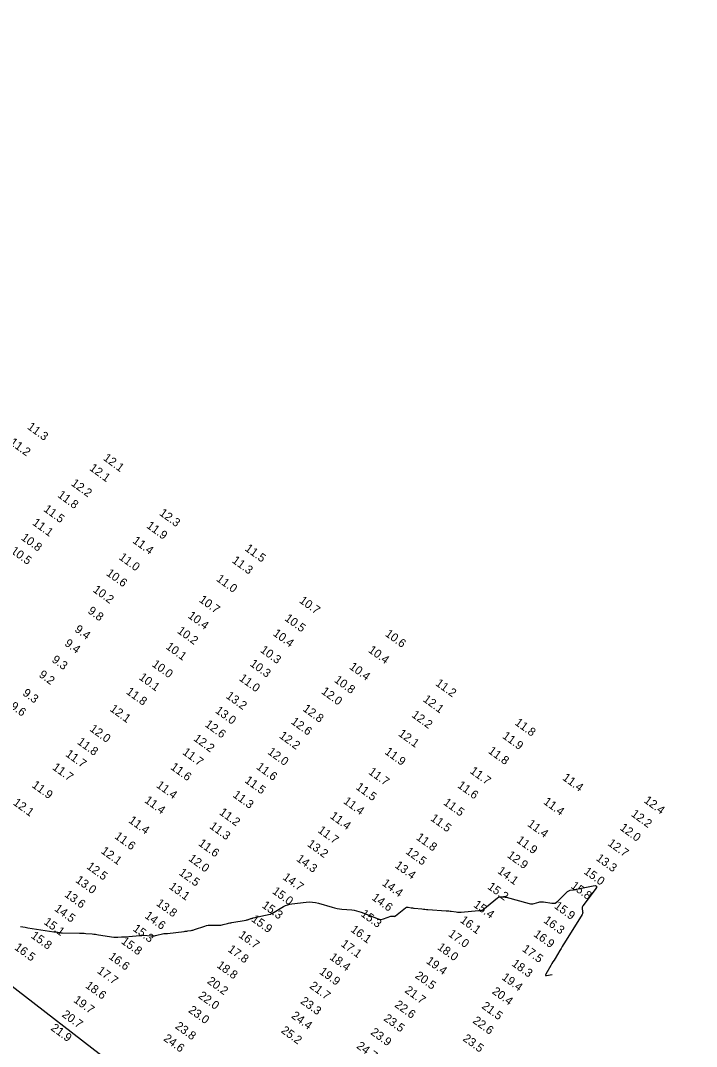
# Model space of a CAD drawing. Extents: x 988130 to 1132882, y 654656 to 841453.
# Drawn here: x 1054664 to 1055064, y 743540 to 744148 of the extents above; entities that cross this region are included whole.
import ezdxf

# ---------------------------------------------------------------- set-up
doc = ezdxf.new("R2010")
doc.units = 0
for name, color, linetype in [('V-ANNO-KEYM', 7, 'Continuous'), ('V-TOPO-MAJR', 7, 'Continuous'), ('V-TOPO-SOUN', 7, 'Continuous')]:
    doc.layers.add(name, color=color, linetype=linetype)

msp = doc.modelspace()

# ---------------------------------------------------------------- linework, layer by layer
at = {"layer": 'V-ANNO-KEYM'}
msp.add_line((1078128.69, 725426.29), (1053870.57, 744184.73), dxfattribs=at)
at = {"layer": 'V-TOPO-MAJR'}
msp.add_lwpolyline([(1054663.53, 743610.94), (1054664.99, 743610.67), (1054666.45, 743610.41), (1054667.92, 743610.17), (1054683.43, 743607.67), (1054683.53, 743607.66), (1054683.64, 743607.65), (1054683.75, 743607.65), (1054683.85, 743607.66), (1054684.29, 743607.7), (1054684.39, 743607.71), (1054684.5, 743607.71), (1054684.61, 743607.7), (1054684.71, 743607.68), (1054686.76, 743607.31), (1054687.14, 743607.25), (1054687.52, 743607.2), (1054687.9, 743607.17), (1054688.29, 743607.16), (1054698.52, 743607.02), (1054699.47, 743607), (1054700.42, 743606.96), (1054701.36, 743606.9), (1054702.31, 743606.82), (1054706.09, 743606.48), (1054707.03, 743606.39), (1054707.98, 743606.29), (1054708.92, 743606.17), (1054709.86, 743606.03), (1054719.01, 743604.66), (1054719.56, 743604.59), (1054720.12, 743604.55), (1054720.68, 743604.54), (1054721.24, 743604.56), (1054723.48, 743604.7), (1054724.04, 743604.73), (1054724.6, 743604.77), (1054725.16, 743604.81), (1054725.72, 743604.86), (1054734.45, 743605.6), (1054734.64, 743605.61), (1054734.83, 743605.63), (1054735.01, 743605.65), (1054735.2, 743605.68), (1054735.95, 743605.77), (1054736.14, 743605.79), (1054736.32, 743605.8), (1054736.51, 743605.8), (1054736.7, 743605.78), (1054740.8, 743605.32), (1054741.54, 743605.27), (1054742.28, 743605.28), (1054743.01, 743605.36), (1054743.74, 743605.5), (1054748.62, 743606.67), (1054748.79, 743606.7), (1054748.97, 743606.73), (1054749.14, 743606.74), (1054749.32, 743606.74), (1054750.03, 743606.73), (1054750.21, 743606.73), (1054750.39, 743606.74), (1054750.56, 743606.75), (1054750.74, 743606.77), (1054760.7, 743607.97), (1054761.22, 743608.04), (1054761.73, 743608.11), (1054762.25, 743608.18), (1054762.76, 743608.26), (1054764.82, 743608.57), (1054765.33, 743608.66), (1054765.84, 743608.78), (1054766.34, 743608.91), (1054766.83, 743609.07), (1054772.97, 743611.18), (1054773.89, 743611.46), (1054774.81, 743611.64), (1054775.76, 743611.75), (1054776.71, 743611.77), (1054781.14, 743611.69), (1054781.81, 743611.7), (1054782.46, 743611.76), (1054783.12, 743611.86), (1054783.76, 743612.01), (1054786.34, 743612.71), (1054786.99, 743612.88), (1054787.63, 743613.03), (1054788.29, 743613.16), (1054788.94, 743613.28), (1054797.41, 743614.71), (1054797.77, 743614.77), (1054798.13, 743614.86), (1054798.48, 743614.96), (1054798.83, 743615.08), (1054800.21, 743615.58), (1054800.56, 743615.7), (1054800.91, 743615.81), (1054801.27, 743615.9), (1054801.62, 743615.99), (1054811.57, 743618.17), (1054811.7, 743618.2), (1054811.81, 743618.24), (1054811.93, 743618.29), (1054812.05, 743618.34), (1054812.5, 743618.57), (1054812.61, 743618.63), (1054812.72, 743618.69), (1054812.83, 743618.75), (1054812.94, 743618.81), (1054819.61, 743622.72), (1054820.77, 743623.32), (1054821.99, 743623.8), (1054823.24, 743624.15), (1054824.54, 743624.37), (1054833.01, 743625.34), (1054834.86, 743625.47), (1054836.69, 743625.4), (1054838.5, 743625.16), (1054840.3, 743624.73), (1054848.41, 743622.35), (1054849.83, 743621.97), (1054851.26, 743621.66), (1054852.7, 743621.42), (1054854.15, 743621.25), (1054859.99, 743620.71), (1054861.44, 743620.52), (1054862.87, 743620.23), (1054864.27, 743619.84), (1054865.64, 743619.35), (1054875.58, 743615.41), (1054876.37, 743615.17), (1054877.17, 743615.09), (1054877.97, 743615.16), (1054878.77, 743615.38), (1054883.14, 743617.01), (1054883.36, 743617.08), (1054883.59, 743617.11), (1054883.82, 743617.12), (1054884.06, 743617.09), (1054885, 743616.93), (1054885.23, 743616.92), (1054885.45, 743616.95), (1054885.66, 743617.03), (1054885.85, 743617.15), (1054891.77, 743621.95), (1054892.14, 743622.19), (1054892.53, 743622.34), (1054892.94, 743622.4), (1054893.38, 743622.37), (1054895.17, 743622.06), (1054895.62, 743621.99), (1054896.07, 743621.92), (1054896.52, 743621.86), (1054896.98, 743621.8), (1054901.52, 743621.31), (1054902.43, 743621.21), (1054903.34, 743621.13), (1054904.25, 743621.05), (1054905.16, 743620.99), (1054916.02, 743620.25), (1054916.76, 743620.19), (1054917.5, 743620.12), (1054918.24, 743620.04), (1054918.97, 743619.95), (1054921.91, 743619.56), (1054922.65, 743619.48), (1054923.39, 743619.45), (1054924.12, 743619.45), (1054924.86, 743619.49), (1054935.18, 743620.39), (1054935.4, 743620.41), (1054935.62, 743620.42), (1054935.85, 743620.44), (1054936.07, 743620.45), (1054936.95, 743620.49), (1054937.17, 743620.51), (1054937.37, 743620.57), (1054937.56, 743620.67), (1054937.74, 743620.79), (1054946.34, 743627.91), (1054946.7, 743628.16), (1054947.08, 743628.34), (1054947.49, 743628.44), (1054947.92, 743628.47), (1054949.7, 743628.46), (1054950.15, 743628.45), (1054950.59, 743628.4), (1054951.02, 743628.32), (1054951.45, 743628.22), (1054965.2, 743624.48), (1054965.9, 743624.33), (1054966.61, 743624.29), (1054967.31, 743624.34), (1054968.02, 743624.5), (1054970.83, 743625.31), (1054971.53, 743625.47), (1054972.24, 743625.56), (1054972.95, 743625.56), (1054973.67, 743625.48), (1054978.56, 743624.7), (1054979.57, 743624.65), (1054980.51, 743624.83), (1054981.38, 743625.24), (1054982.17, 743625.88), (1054987.83, 743631.58), (1054988.19, 743631.89), (1054988.58, 743632.13), (1054989, 743632.3), (1054989.46, 743632.4), (1054991.37, 743632.67), (1054991.85, 743632.74), (1054992.32, 743632.82), (1054992.79, 743632.9), (1054993.27, 743633), (1055003.02, 743635.03), (1055004.44, 743635.17), (1055005.14, 743634.86), (1055005.11, 743634.1), (1055004.37, 743632.88), (1054996.9, 743623.12), (1054996.67, 743622.75), (1054996.53, 743622.36), (1054996.48, 743621.95), (1054996.52, 743621.52), (1054996.84, 743619.75), (1054996.89, 743619.31), (1054996.85, 743618.89), (1054996.73, 743618.49), (1054996.53, 743618.1), (1054986.09, 743601.19), (1054985.4, 743600.07), (1054984.71, 743598.95), (1054984.02, 743597.82), (1054983.34, 743596.7), (1054980.51, 743592), (1054979.89, 743590.96), (1054979.27, 743589.93), (1054978.66, 743588.89), (1054978.05, 743587.85), (1054974.95, 743582.55), (1054974.78, 743582.15), (1054974.81, 743581.89), (1054975.04, 743581.78), (1054975.48, 743581.81), (1054978.71, 743582.41)], dxfattribs=at)

# ---------------------------------------------------------------- texts
at = {"layer": 'V-TOPO-SOUN'}
for s, p in [('11.3 ', (1054667.27, 743906.37)), ('11.2 ', (1054656.78, 743897.14)), ('12.1 ', (1054712.26, 743887.87)), ('12.1 ', (1054704.1, 743881.88)), ('12.2 ', (1054693.21, 743872.86)), ('11.8 ', (1054685.2, 743865.94)), ('11.5 ', (1054676.89, 743857.54)), ('12.3 ', (1054745.53, 743855.23)), ('11.1 ', (1054670.27, 743849.51)), ('11.9 ', (1054737.9, 743847.73)), ('10.8 ', (1054663.58, 743840.65)), ('11.4 ', (1054729.68, 743838.83)), ('10.5 ', (1054657.41, 743832.78)), ('11.5 ', (1054796.24, 743834.22)), ('11.0 ', (1054721.57, 743829)), ('11.3 ', (1054788.6, 743827.11)), ('10.6 ', (1054714.07, 743819.54)), ('11.0 ', (1054779.31, 743816.21)), ('10.2 ', (1054706.16, 743809.71)), ('10.7 ', (1054769.07, 743803.81)), ('10.7 ', (1054828.47, 743803.35)), ('9.8', (1054703.11, 743797.16)), ('10.4 ', (1054762.45, 743794.34)), ('10.5 ', (1054819.83, 743792.78)), ('9.4', (1054695.32, 743786.22)), ('10.2 ', (1054756.14, 743785.35)), ('10.4 ', (1054812.9, 743783.85)), ('10.6 ', (1054879.35, 743783.59)), ('9.4', (1054689.35, 743777.92)), ('10.1 ', (1054749.35, 743776.01)), ('10.3 ', (1054805.34, 743774)), ('10.4 ', (1054869.4, 743773.96)), ('9.3', (1054681.78, 743768.23)), ('10.0 ', (1054741.16, 743765.58)), ('10.3 ', (1054799.21, 743765.87)), ('9.2', (1054674.12, 743759.36)), ('10.4 ', (1054858.14, 743764.06)), ('10.1 ', (1054733.45, 743757.81)), ('11.0 ', (1054792.8, 743757.22)), ('10.8 ', (1054849.2, 743756.24)), ('11.2 ', (1054909.22, 743754.26)), ('9.3', (1054664.47, 743748.46)), ('11.8 ', (1054725.86, 743749.29)), ('13.2 ', (1054785.02, 743746.76)), ('12.0 ', (1054841.54, 743749.43)), ('9.6', (1054657.11, 743740.63)), ('12.1 ', (1054901.81, 743744.77)), ('12.1 ', (1054716.21, 743739.08)), ('13.0 ', (1054778.65, 743738.06)), ('12.8 ', (1054830.56, 743739.15)), ('12.2 ', (1054895.08, 743735.53)), ('12.6 ', (1054772.53, 743729.91)), ('12.6 ', (1054823.58, 743731.57)), ('11.8 ', (1054956.23, 743730.95)), ('12.0 ', (1054704.23, 743727.26)), ('12.2 ', (1054816.61, 743723.16)), ('12.1 ', (1054887.21, 743724.37)), ('11.9 ', (1054948.88, 743723)), ('11.8 ', (1054696.87, 743719.53)), ('12.2 ', (1054765.79, 743721.53)), ('11.7 ', (1054689.91, 743712.29)), ('11.7 ', (1054759.23, 743713.43)), ('12.0 ', (1054809.73, 743713.59)), ('11.9 ', (1054879.15, 743713.64)), ('11.8 ', (1054940.45, 743714.13)), ('11.7 ', (1054682.11, 743704.41)), ('11.6 ', (1054752.14, 743704.56)), ('11.6 ', (1054803.03, 743704.72)), ('11.7 ', (1054869.51, 743701.72)), ('11.7 ', (1054929.66, 743702.22)), ('11.4 ', (1054984.48, 743698.25)), ('11.9 ', (1054669.98, 743693.87)), ('11.4 ', (1054743.73, 743693.84)), ('11.5 ', (1054796.13, 743696.68)), ('11.5 ', (1054862, 743692.72)), ('11.6 ', (1054922.25, 743693.74)), ('11.3 ', (1054789.08, 743688.1)), ('12.1 ', (1054658.84, 743683.48)), ('11.4 ', (1054736.73, 743684.85)), ('11.4 ', (1054854.61, 743684.35)), ('11.5 ', (1054913.9, 743683.58)), ('11.4 ', (1054973.2, 743684.01)), ('12.4 ', (1055032.8, 743684.8)), ('11.2 ', (1054781.06, 743677.71)), ('11.4 ', (1054846.7, 743675.52)), ('11.5 ', (1054906.25, 743674.18)), ('12.2 ', (1055025.18, 743676.77)), ('11.4 ', (1054727.3, 743672.94)), ('11.3 ', (1054775.26, 743669.53)), ('11.4 ', (1054963.74, 743670.84)), ('12.0 ', (1055018.54, 743668.58)), ('11.6 ', (1054718.99, 743663.54)), ('11.7 ', (1054839.47, 743667.11)), ('11.8 ', (1054897.76, 743662.88)), ('11.6 ', (1054768.66, 743659.34)), ('13.2 ', (1054833.22, 743658.95)), ('11.9 ', (1054957.28, 743661.18)), ('12.7 ', (1055011.35, 743659.41)), ('12.1 ', (1054710.94, 743654.79)), ('12.0 ', (1054762.78, 743650.36)), ('14.3 ', (1054826.75, 743650.17)), ('12.5 ', (1054891.52, 743654.51)), ('12.9 ', (1054951.71, 743652.29)), ('13.3 ', (1055004.4, 743650.54)), ('12.5 ', (1054702.42, 743645.63)), ('13.4 ', (1054885.16, 743646.24)), ('13.0 ', (1054695.83, 743637.54)), ('12.5 ', (1054757.11, 743641.96)), ('14.7 ', (1054818.65, 743639.28)), ('14.1 ', (1054945.99, 743642.95)), ('15.0 ', (1054997.14, 743642.63)), ('13.1 ', (1054751.26, 743633.72)), ('15.0 ', (1054812.46, 743630.92)), ('14.4 ', (1054877.58, 743635.71)), ('15.2 ', (1054940.08, 743633.62)), ('15.8 ', (1054989.49, 743634.11)), ('13.6 ', (1054689.3, 743629.02)), ('14.6 ', (1054871.46, 743627.17)), ('14.5 ', (1054683.32, 743620.62)), ('13.8 ', (1054743.68, 743623.78)), ('15.3 ', (1054806.34, 743622.56)), ('15.4 ', (1054931.73, 743622.93)), ('15.9 ', (1054979.59, 743622.2)), ('15.1 ', (1054677.03, 743612.71)), ('14.6 ', (1054736.88, 743616.38)), ('15.9 ', (1054800.07, 743614.39)), ('15.3 ', (1054864.93, 743617.49)), ('16.1 ', (1054923.81, 743613.78)), ('16.3 ', (1054973.32, 743613.62)), ('15.3 ', (1054729.82, 743608.73)), ('16.1 ', (1054858.91, 743608.26)), ('15.8 ', (1054669.42, 743604.59)), ('15.8 ', (1054722.89, 743601.26)), ('16.7 ', (1054792.52, 743604.93)), ('17.0 ', (1054916.8, 743605.61)), ('16.9 ', (1054967.37, 743605.49)), ('16.5 ', (1054659.65, 743597.62)), ('17.8 ', (1054786.11, 743596.49)), ('17.1 ', (1054853.16, 743599.64)), ('18.0 ', (1054910.35, 743597.77)), ('17.5 ', (1054960.62, 743596.68)), ('16.6 ', (1054715.49, 743592.2)), ('18.4 ', (1054846.45, 743591.79)), ('19.4 ', (1054903.71, 743589.55)), ('17.7 ', (1054708.69, 743583.74)), ('18.8 ', (1054779.58, 743587.02)), ('19.9 ', (1054840.37, 743583.25)), ('18.3 ', (1054954.43, 743588.04)), ('20.2 ', (1054773.88, 743577.61)), ('20.5 ', (1054897.14, 743580.84)), ('19.4 ', (1054948.52, 743579.88)), ('18.6 ', (1054701.68, 743575.01)), ('21.7 ', (1054834.57, 743574.8)), ('21.7 ', (1054891, 743572.2)), ('20.4 ', (1054942.75, 743571.54)), ('19.7 ', (1054694.65, 743566.43)), ('22.0 ', (1054768.65, 743568.94)), ('23.3 ', (1054829.17, 743565.72)), ('22.6 ', (1054885.02, 743563.65)), ('20.7 ', (1054687.79, 743557.84)), ('23.0 ', (1054762.73, 743560.43)), ('21.5 ', (1054936.63, 743562.81)), ('24.4 ', (1054823.77, 743557.09)), ('23.5 ', (1054878.51, 743555.54)), ('22.6 ', (1054931.29, 743554.17)), ('21.9 ', (1054681.19, 743549.83)), ('23.8 ', (1054754.89, 743550.9)), ('25.2 ', (1054817.66, 743548.38)), ('23.9 ', (1054870.76, 743547.31)), ('24.6 ', (1054747.99, 743543.64)), ('23.5 ', (1054925.42, 743543.59)), ('24.7 ', (1054862.43, 743539.17))]:
    msp.add_text(s, height=5, rotation=324, dxfattribs=at).set_placement(p)

doc.saveas('drawing.dxf')
